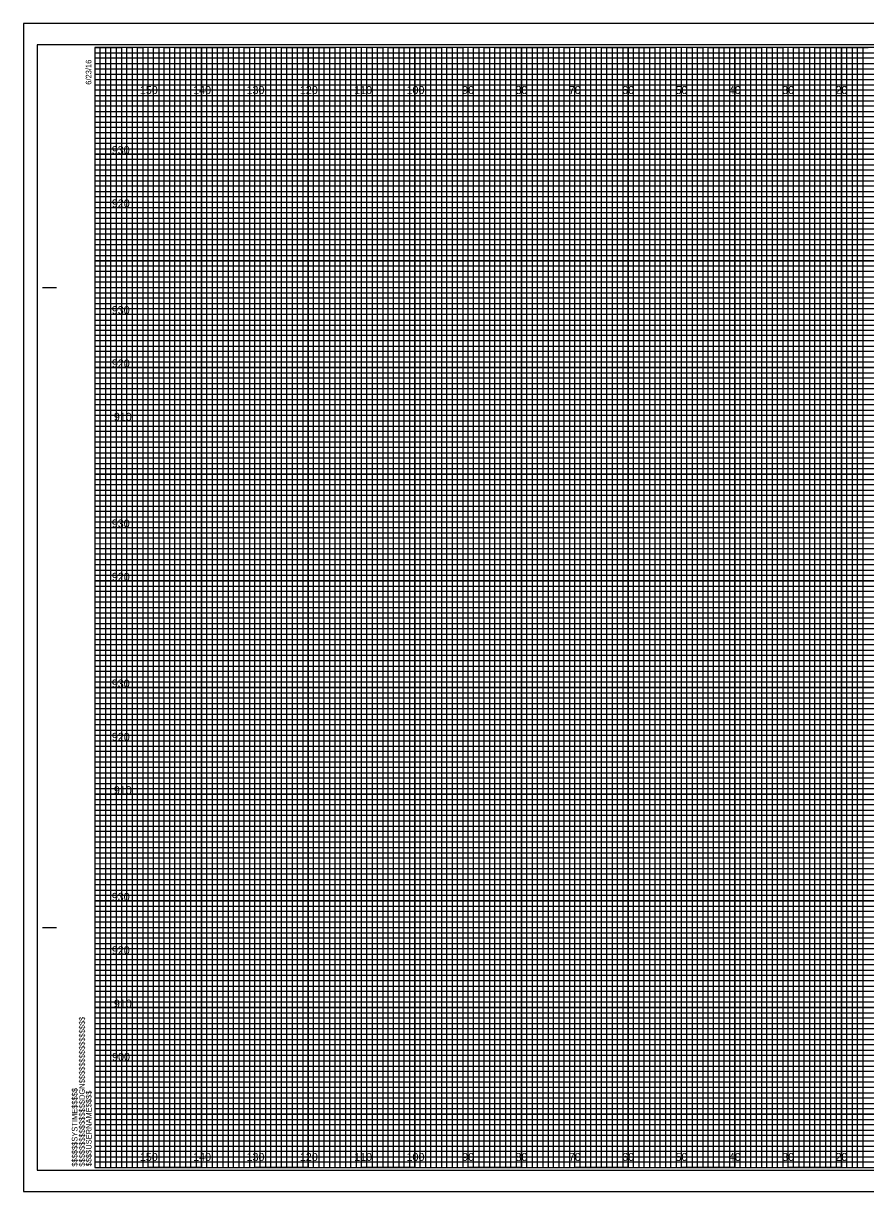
# Model space of a CAD drawing. Extents: x -13 to 323, y -4 to 214.
# Drawn here: x -13.4 to 144.5, y -4.5 to 214.5 of the extents above; entities that cross this region are included whole.
import ezdxf

# ---------------------------------------------------------------- set-up
doc = ezdxf.new("R2010")
doc.units = 0
for name, color, linetype in [('Prop XS Elevation Labels', 7, 'Continuous'), ('Prop XS Offset Labels', 7, 'Continuous'), ('Sheet Cross Section CELL', 7, 'Continuous'), ('Sheet Cross Section Grid Major CELL', 7, 'Continuous'), ('Sheet Cross Section Grid Middle CELL', 7, 'Continuous'), ('Sheet Cross Section Grid Minor 1 CELL', 7, 'Continuous'), ('Sheet Cross Section Grid Minor 2 CELL', 7, 'Continuous'), ('Sheet Cutting Line CELL', 7, 'Continuous'), ('Sheet DOT Grid CELL', 7, 'Continuous'), ('Sheet Plot Border Inside CELL', 7, 'Continuous'), ('Sheet Plot Border Outside CELL', 7, 'Continuous')]:
    doc.layers.add(name, color=color, linetype=linetype)

msp = doc.modelspace()

# ---------------------------------------------------------------- linework, layer by layer
at = {"layer": 'Sheet Cross Section CELL'}
for p, q in [((-9.8, 165), (-7.3, 165)), ((-9.7, 165), (-7.2, 165)), ((-9.8, 45), (-7.3, 45)), ((-9.7, 45), (-7.2, 45)), ((0, 0), (0, 0)), ((0, 0), (0, 0)), ((0, 0), (0, 0)), ((0, 0), (0, 0)), ((0, 0), (0, 0)), ((0, 0), (0, 0)), ((0, 0), (0, 0))]:
    msp.add_line(p, q, dxfattribs=at)
msp.add_lwpolyline([(320, 210), (0, 210), (0, 0), (320, 0)], close=True, dxfattribs=at)
at = {"layer": 'Sheet Cross Section Grid Major CELL'}
for p, q in [((10, 210), (0, 210)), ((10, 0), (10, 210)), ((30, 210), (20, 210)), ((20, 210), (20, 0)), ((30, 0), (30, 210)), ((50, 210), (40, 210)), ((40, 210), (40, 0)), ((50, 0), (50, 210)), ((70, 210), (60, 210)), ((60, 210), (60, 0)), ((70, 0), (70, 210)), ((90, 210), (80, 210)), ((80, 210), (80, 0)), ((90, 0), (90, 210)), ((110, 210), (100, 210)), ((100, 210), (100, 0)), ((110, 0), (110, 210)), ((130, 210), (120, 210)), ((120, 210), (120, 0)), ((130, 0), (130, 210)), ((150, 210), (140, 210)), ((140, 210), (140, 0)), ((20, 0), (10, 0)), ((40, 0), (30, 0)), ((60, 0), (50, 0)), ((80, 0), (70, 0)), ((100, 0), (90, 0)), ((120, 0), (110, 0)), ((140, 0), (130, 0))]:
    msp.add_line(p, q, dxfattribs=at)
for points in [[(0, 200), (320, 200), (320, 190), (0, 190)], [(0, 180), (320, 180), (320, 170), (0, 170)], [(0, 160), (320, 160), (320, 150), (0, 150)], [(0, 140), (320, 140), (320, 130), (0, 130)], [(0, 120), (320, 120), (320, 110), (0, 110)], [(0, 100), (320, 100), (320, 90), (0, 90)], [(0, 80), (320, 80), (320, 70), (0, 70)], [(0, 60), (320, 60), (320, 50), (0, 50)], [(0, 40), (320, 40), (320, 30), (0, 30)], [(0, 20), (320, 20), (320, 10), (0, 10)]]:
    msp.add_lwpolyline(points, dxfattribs=at)
at = {"layer": 'Sheet Cross Section Grid Middle CELL'}
for points in [[(0, 210), (5, 210), (5, 0), (15, 0), (15, 210), (25, 210), (25, 0), (35, 0), (35, 210), (45, 210), (45, 0), (55, 0), (55, 210), (65, 210), (65, 0), (75, 0), (75, 210), (85, 210), (85, 0), (95, 0), (95, 210), (105, 210), (105, 0), (115, 0), (115, 210), (125, 210), (125, 0), (135, 0), (135, 210), (145, 210)], [(0, 205), (275, 205)], [(0, 185), (320, 185), (320, 195), (0, 195)], [(0, 165), (320, 165), (320, 175), (0, 175)], [(0, 145), (320, 145), (320, 155), (0, 155)], [(0, 125), (320, 125), (320, 135), (0, 135)], [(0, 105), (320, 105), (320, 115), (0, 115)], [(0, 85), (320, 85), (320, 95), (0, 95)], [(0, 65), (320, 65), (320, 75), (0, 75)], [(0, 45), (320, 45), (320, 55), (0, 55)], [(0, 25), (320, 25), (320, 35), (0, 35)], [(0, 5), (320, 5), (320, 15), (0, 15)]]:
    msp.add_lwpolyline(points, dxfattribs=at)
at = {"layer": 'Sheet Cross Section Grid Minor 1 CELL'}
for p, q in [((0, 209), (260, 209)), ((260, 207.98), (0, 207.98)), ((0, 207.98), (0, 207)), ((0, 207), (260, 207)), ((260, 205.89), (0, 205.89)), ((0, 205.89), (0, 204)), ((0, 204), (320, 204))]:
    msp.add_line(p, q, dxfattribs=at)
for points in [[(0, 203), (270, 203), (320, 203), (320, 202), (0, 202)], [(0, 201), (320, 201), (320, 199), (0, 199)], [(0, 198), (320, 198), (320, 197), (0, 196.98)], [(0, 196), (320, 196), (320, 194), (0, 194)], [(0, 193), (320, 193), (320, 192), (0, 192)], [(0, 191), (320, 191), (320, 189), (0, 189)], [(0, 188), (320, 188), (320, 187), (0, 187)], [(0, 186), (320, 186), (320, 184), (0, 184)], [(0, 183), (320, 183), (320, 182), (0, 182)], [(0, 181), (320, 181), (320, 179), (0, 179)], [(0, 178), (320, 178), (320, 177), (0, 177)], [(0, 176), (320, 176), (320, 173.95), (320, 173), (320, 172), (0, 172)], [(0, 174), (320, 174), (320, 173), (0, 173)], [(0, 171), (320, 171), (320, 169), (0, 169.03)], [(0, 169.03), (320, 169), (320, 168), (0, 168)], [(0, 167), (320, 167), (320, 166), (0, 166)], [(0, 164), (320, 164), (320, 163), (0, 163)], [(0, 162), (320, 162), (320, 161), (0, 161)], [(-0.07, 158.89), (320, 158.89), (320, 157.88), (-0.07, 157.88)], [(0, 157), (320, 157), (320, 156), (0, 156)], [(0, 154), (320, 154), (320, 153), (0, 153)], [(0, 152), (320, 152), (320, 151), (0, 151)], [(0, 149), (320, 149), (320, 148), (0, 148)], [(0, 147), (320, 147), (320, 146), (0, 146)], [(0, 144), (320, 144), (320, 143), (0, 143)], [(0, 142), (320, 142), (320, 141), (0, 141)], [(0, 139), (320, 139), (319.99, 137.98), (0, 138)], [(0, 137), (320, 137), (320, 136), (0, 136)], [(0, 134), (320, 134), (320, 133), (0, 133)], [(0, 132), (320, 132), (320, 131), (0, 131)], [(0, 129), (320, 129), (320, 128), (0, 128)], [(0, 127), (320, 127), (320, 126), (0, 126)], [(0, 124), (320, 124), (320, 123), (0, 123)], [(0, 122), (320, 122), (320, 121), (0, 121)], [(0, 119), (320, 119), (320, 118), (0, 118)], [(0, 116.99), (320.07, 116.91), (320, 116), (0, 116)], [(0, 114), (320, 114), (320, 113), (0, 113)], [(0, 112), (320, 112), (320, 111), (0, 111)], [(0, 109), (320, 109), (320, 108), (0, 108)], [(0, 107), (320, 107), (320, 106), (0, 106)], [(0, 104), (320, 104), (320, 103), (0, 103)], [(0, 102), (320, 102), (320, 101), (0, 101)], [(0, 99), (320, 99), (320, 98), (0, 98)], [(0, 97), (320, 97), (320, 96), (0, 96)], [(0, 94), (320, 94), (320, 93), (0, 93)], [(0, 92), (320, 92), (320, 91), (0, 91)], [(0, 89), (320, 89), (320, 88), (0, 88)], [(0, 87), (320, 87), (320, 86), (0, 86)], [(0, 84), (320, 84), (320, 83), (0, 83)], [(0, 82), (320, 82), (320, 81), (0, 81)], [(0, 79), (320, 79), (319.99, 77.98), (0, 78)], [(0, 77), (320, 77), (320, 76), (0, 76)], [(0, 74), (320, 74), (320, 73), (0, 73)], [(0, 72), (320, 72), (320, 71), (0, 71)], [(0, 69), (320, 69), (320, 68), (0, 68)], [(0, 67), (320, 67), (320, 66), (0, 66)], [(0, 64), (320, 64), (320, 63), (0, 63)], [(0, 62), (320, 62), (320, 61), (0, 61)], [(0, 59), (320, 59), (320, 58), (0, 58)], [(0, 56.99), (320.07, 56.91), (320, 56), (0, 56)], [(0, 54), (320, 54), (320, 53), (0, 53)], [(0, 52), (320, 52), (320, 51), (0, 51)], [(0, 49), (320, 49), (320, 48), (0, 48)], [(0, 47), (320, 47), (320, 46), (0, 46)], [(0, 44), (320, 44), (320, 43), (0, 43)], [(0, 42), (320, 42), (320, 41), (0, 41)], [(0, 39), (320, 39), (320, 38), (0, 38)], [(0, 37), (320, 37), (320, 36), (0, 36)], [(0, 34), (320, 34), (320, 33), (0, 33)], [(0, 32), (320, 32), (320, 31), (0, 31)], [(0, 29), (320, 29), (320, 28), (0, 28)], [(0, 27), (320, 27), (320, 26), (0, 26)], [(0, 24), (320, 24), (320, 23), (0, 23)], [(0, 22), (320, 22), (320, 21), (0, 21)], [(0, 19), (320, 19), (320, 18), (0, 18)], [(0, 17), (320, 17), (320, 16), (0, 16)], [(0, 14), (320, 14), (320, 13), (0, 13)], [(0, 12), (320, 12), (320, 11), (0, 11)], [(0, 9), (320, 9), (320, 8), (0, 8)], [(0, 7), (320, 7), (320, 6), (0, 6)], [(0, 4), (320, 4), (320, 3), (0, 3)], [(0, 2), (320, 2), (320, 1), (0, 1)]]:
    msp.add_lwpolyline(points, dxfattribs=at)
at = {"layer": 'Sheet Cross Section Grid Minor 2 CELL'}
for points in [[(0, 0), (1, 0), (1, 210), (2, 210), (2, 0)], [(2, 0), (3, 0), (3, 210), (4, 210), (4, 0)], [(5, 0), (6, 0), (6, 210), (7, 210), (7, 0)], [(7, 0), (8, 0), (8, 210), (9, 210), (9, 0)], [(10, 0), (11, 0), (11, 210), (12, 210), (12, 0)], [(12, 0), (13, 0), (13, 210), (14, 210), (14, 0)], [(15, 0), (16, 0), (16, 210), (17, 210), (17, 0)], [(17, 0), (18, 0), (18, 210), (19, 210), (19, 0)], [(20, 0), (21, 0), (21, 210), (22, 210), (22, 0)], [(22, 0), (23, 0), (23, 210), (24, 210), (24, 0)], [(25, 0), (26, 0), (26, 210), (27, 210), (27, 0)], [(27, 0), (28, 0), (28, 210), (29, 210), (29, 0)], [(30, 0), (31, 0), (31, 210), (32, 210), (32, 0)], [(32, 0), (33, 0), (33, 210), (34, 210), (34, 0)], [(35, 0), (36, 0), (36, 210), (37, 210), (37, 0)], [(37, 0), (38, 0), (38, 210), (39, 210), (39, 0)], [(40, 0), (41, 0), (41, 210), (42, 210), (42, 0)], [(42, 0), (43, 0), (43, 210), (44, 210), (44, 0)], [(45, 0), (46, 0), (46, 210), (47, 210), (47, 0)], [(47, 0), (48, 0), (48, 210), (49, 210), (49, 0)], [(50, 0), (51, 0), (51, 210), (52, 210), (52, 0)], [(52, 0), (53, 0), (53, 210), (54, 210), (54, 0)], [(55, 0), (56, 0), (56, 210), (57, 210), (57, 0)], [(57, 0), (58, 0), (58, 210), (59, 210), (59, 0)], [(60, 0), (61, 0), (61, 210), (62, 210), (62, 0)], [(62, 0), (63, 0), (63, 210), (64, 210), (64, 0)], [(65, 0), (66, 0), (66, 210), (67, 210), (67, 0)], [(67, 0), (68, 0), (68, 210), (69, 210), (69, 0)], [(70, 0), (71, 0), (71, 210), (72, 210), (72, 0)], [(72, 0), (73, 0), (73, 210), (74, 210), (74, 0)], [(75, 0), (76, 0), (76, 210), (77, 210), (77, 0)], [(77, 0), (78, 0), (78, 210), (79, 210), (79, 0)], [(80, 0), (81, 0), (81, 210), (82, 210), (82, 0)], [(82, 0), (83, 0), (83, 210), (84, 210), (84, 0)], [(85, 0), (86, 0), (86, 210), (87, 210), (87, 0)], [(87, 0), (88, 0), (88, 210), (89, 210), (89, 0)], [(90, 0), (91, 0), (91, 210), (92, 210), (92, 0)], [(92, 0), (93, 0), (93, 210), (94, 210), (94, 0)], [(95, 0), (96, 0), (96, 210), (97, 210), (97, 0)], [(97, 0), (98, 0), (98, 210), (99, 210), (99, 0)], [(100, 0), (101, 0), (101, 210), (102, 210), (102, 0)], [(102, 0), (103, 0), (103, 210), (104, 210), (104, 0)], [(105, 0), (106, 0), (106, 210), (107, 210), (107, 0)], [(107, 0), (108, 0), (108, 210), (109, 210), (109, 0)], [(110, 0), (111, 0), (111, 210), (112, 210), (112, 0)], [(112, 0), (113, 0), (113, 210), (114, 210), (114, 0)], [(115, 0), (116, 0), (116, 210), (117, 210), (117, 0)], [(117, 0), (118, 0), (118, 210), (119, 210), (119, 0)], [(120, 0), (121, 0), (121, 210), (122, 210), (122, 0)], [(122, 0), (123, 0), (123, 210), (124, 210), (124, 0)], [(125, 0), (126, 0), (126, 210), (127, 210), (127, 0)], [(127, 0), (128, 0), (128, 210), (129, 210), (129, 0)], [(130, 0), (131, 0), (131, 210), (132, 210), (132, 0)], [(132, 0), (133, 0), (133, 210), (134, 210), (134, 0)], [(135, 0), (136, 0), (136, 210), (137, 210), (137, 0)], [(137, 0), (138, 0), (138, 210), (139, 210), (139, 0)], [(140, 0), (141, 0), (141, 210), (142, 210), (142, 0)], [(142, 0), (143, 0), (143, 210), (144, 210), (144, 0)]]:
    msp.add_lwpolyline(points, dxfattribs=at)
at = {"layer": 'Sheet Cutting Line CELL'}
for p, q in [((323.3, 214.5), (-13.4, 214.5)), ((-13.4, 214.5), (-13.4, -4.5)), ((-13.4, -4.5), (323.3, -4.5))]:
    msp.add_line(p, q, dxfattribs=at)
at = {"layer": 'Sheet DOT Grid CELL'}
for p, q in [((10, 0), (10, 210)), ((20, 0), (20, 210)), ((30, 0), (30, 210)), ((40, 0), (40, 210)), ((50, 0), (50, 210)), ((60, 0), (60, 210)), ((70, 0), (70, 210)), ((80, 0), (80, 210)), ((90, 0), (90, 210)), ((100, 0), (100, 210)), ((110, 0), (110, 210)), ((120, 0), (120, 210)), ((130, 0), (130, 210)), ((140, 0), (140, 210)), ((0, 200), (320, 200)), ((0, 190), (320, 190)), ((0, 180), (320, 180)), ((0, 170), (320, 170)), ((0, 160), (320, 160)), ((0, 150), (320, 150)), ((0, 140), (320, 140)), ((0, 130), (320, 130)), ((0, 120), (320, 120)), ((0, 110), (320, 110)), ((0, 100), (320, 100)), ((0, 90), (320, 90)), ((0, 80), (320, 80)), ((0, 70), (320, 70)), ((0, 60), (320, 60)), ((0, 50), (320, 50)), ((0, 40), (320, 40)), ((0, 30), (320, 30)), ((0, 20), (320, 20)), ((0, 10), (320, 10))]:
    msp.add_line(p, q, dxfattribs=at)
at = {"layer": 'Sheet Plot Border Inside CELL'}
msp.add_lwpolyline([(-10.8, -0.5), (322.4, -0.5), (322.4, 210.5), (-10.8, 210.5)], close=True, dxfattribs=at)
at = {"layer": 'Sheet Plot Border Outside CELL'}
msp.add_lwpolyline([(-13.4, -4.5), (323.3, -4.5), (323.3, 214.5), (-13.4, 214.5)], close=True, dxfattribs=at)

# ---------------------------------------------------------------- texts
at = {"layer": 'Prop XS Elevation Labels'}
for s, p in [('930', (3.18, 190)), ('920', (3.19, 180)), ('930', (3.18, 160)), ('920', (3.19, 150)), ('910', (3.57, 140)), ('930', (3.18, 120)), ('920', (3.19, 110)), ('930', (3.18, 90)), ('920', (3.19, 80)), ('910', (3.57, 70)), ('930', (3.18, 50)), ('920', (3.19, 40)), ('910', (3.57, 30)), ('900', (3.24, 20))]:
    msp.add_text(s, height=1.5, dxfattribs=at).set_placement(p)
at = {"layer": 'Prop XS Offset Labels'}
for s, p in [('150', (8.44, 201.25)), ('140', (18.44, 201.25)), ('130', (28.44, 201.25)), ('120', (38.44, 201.25)), ('110', (48.62, 201.25)), ('100', (58.44, 201.25)), ('90', (68.86, 201.25)), ('80', (78.86, 201.25)), ('70', (88.86, 201.25)), ('60', (98.86, 201.25)), ('50', (108.86, 201.25)), ('40', (118.86, 201.25)), ('30', (128.86, 201.25)), ('20', (138.86, 201.25)), ('150', (8.44, 1.25)), ('140', (18.44, 1.25)), ('130', (28.44, 1.25)), ('120', (38.44, 1.25)), ('110', (48.62, 1.25)), ('100', (58.44, 1.25)), ('90', (68.86, 1.25)), ('80', (78.86, 1.25)), ('70', (88.86, 1.25)), ('60', (98.86, 1.25)), ('50', (108.86, 1.25)), ('40', (118.86, 1.25)), ('30', (128.86, 1.25)), ('20', (138.86, 1.25))]:
    msp.add_text(s, height=1.5, dxfattribs=at).set_placement(p)
at = {"layer": 'Sheet Cross Section CELL'}
for s, p in [('6/23/16', (-0.65, 203)), ('$$$$$$$$$$$$$$$$DGN$$$$$$$$$$$$$$$$', (-1.88, 0.18)), ('$$$$$$SYSTIME$$$$$', (-3.26, 0.18)), ('$$$$USERNAME$$$$', (-0.62, 0.23))]:
    msp.add_text(s, height=1.05, rotation=90, dxfattribs=at).set_placement(p)

doc.saveas('drawing.dxf')
